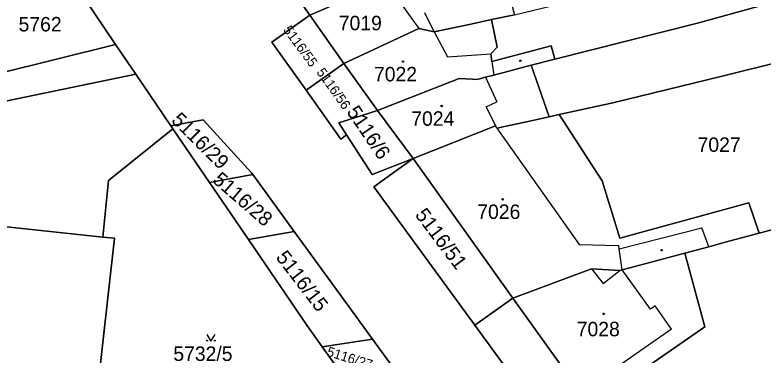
# Model space of a CAD drawing. Extents: x -596233 to -595156, y -1161235 to -1159375.
# Drawn here: x -595331.7 to -595243.9, y -1160472 to -1160432.1 of the extents above; entities that cross this region are included whole.
import ezdxf

# ---------------------------------------------------------------- set-up
doc = ezdxf.new("R2010")
doc.units = 0
for name, color, linetype in [('KN_CAR_KR', 7, 'Continuous'), ('KN_KULTURY', 7, 'Continuous'), ('KN_PARC_CIS_POZ', 7, 'Continuous'), ('KN_PARC_CIS_STAV', 7, 'Continuous'), ('KN_PARC_PLOCHA', 7, 'Continuous'), ('parcely_l', 7, 'Continuous')]:
    doc.layers.add(name, color=color, linetype=linetype)

msp = doc.modelspace()

# ---------------------------------------------------------------- linework, layer by layer
at = {"layer": 'KN_CAR_KR'}
for points in [[(-595288.01, -1160428.54), (-595284.3, -1160433.74)], [(-595282.52, -1160434.13), (-595283.59, -1160431.9)], [(-595282.52, -1160434.13), (-595280.96, -1160437.04)], [(-595280.96, -1160437.04), (-595275.87, -1160436.71)], [(-595275.74, -1160437.59), (-595275.5, -1160439.19)], [(-595276.48, -1160439.44), (-595275.14, -1160442.34)], [(-595276.4, -1160442.93), (-595275.14, -1160442.34)], [(-595276.4, -1160442.93), (-595275.31, -1160445.16)], [(-595275.13, -1160445.42), (-595265.47, -1160459.09)], [(-595260.77, -1160459.59), (-595251.06, -1160457.12)], [(-595250.26, -1160459.34), (-595251.06, -1160457.12)], [(-595265.47, -1160459.09), (-595260.84, -1160459.18)], [(-595260.77, -1160459.59), (-595260.84, -1160459.18)], [(-595260.43, -1160462.05), (-595260.77, -1160459.59)], [(-595264.02, -1160461.93), (-595262.68, -1160463.66)], [(-595262.68, -1160463.66), (-595260.7, -1160462.12)], [(-595257.11, -1160466.67), (-595260.43, -1160462.05)], [(-595256.55, -1160466.27), (-595257.11, -1160466.67)], [(-595254.62, -1160469.02), (-595256.55, -1160466.27)], [(-595254.62, -1160469.02), (-595264.73, -1160476.04)]]:
    msp.add_lwpolyline(points, dxfattribs=at)
at = {"layer": 'KN_KULTURY'}
msp.add_lwpolyline([(-595309.2118, -1160469.6516), (-595308.7118, -1160470.4016), (-595308.2118, -1160469.6516)], dxfattribs=at)
for centre, radius in [((-595286.18, -1160437.61), 0.09), ((-595286.18, -1160437.61), 0.0398), ((-595272.4, -1160437.52), 0.09), ((-595272.4, -1160437.52), 0.0398), ((-595281.64, -1160442.82), 0.09), ((-595281.64, -1160442.82), 0.0398), ((-595274.46, -1160453.77), 0.09), ((-595274.46, -1160453.77), 0.0398), ((-595255.8, -1160459.75), 0.09), ((-595255.8, -1160459.75), 0.0398), ((-595262.6, -1160467.21), 0.09), ((-595262.6, -1160467.21), 0.0398), ((-595309.162, -1160470.3514), 0.05), ((-595308.2626, -1160470.3514), 0.05)]:
    msp.add_circle(centre, radius, dxfattribs=at)
at = {"layer": 'KN_PARC_PLOCHA'}
for points in [[(-595334.41, -1160392.48), (-595328.83, -1160390.72), (-595328.44, -1160391.88), (-595323.41, -1160403.6), (-595321.29, -1160407.39), (-595317.06, -1160413.69), (-595315.81, -1160415.5), (-595318.48, -1160416.19), (-595309.95, -1160427.87), (-595307.38, -1160427.14), (-595305.39, -1160429.95), (-595300.92, -1160426.78), (-595297.09, -1160432.18), (-595301.56, -1160435.33), (-595297.55, -1160440.95), (-595293.45, -1160446.71), (-595292.81, -1160446.21), (-595289.79, -1160450.86), (-595284.99, -1160448.98), (-595289.59, -1160452.33), (-595277.72, -1160468.56), (-595260.2, -1160492.58)], [(-595287.14, -1160473.77), (-595289.76, -1160470.17), (-595291.7, -1160467.5), (-595298.95, -1160457.54), (-595303.81, -1160450.85), (-595303.95, -1160450.66), (-595309.64, -1160444.43), (-595313.41, -1160445.17), (-595317.54, -1160439.11), (-595319.94, -1160435.6), (-595326.06, -1160426.44), (-595332.18, -1160420.84)], [(-595395.86, -1160474.84), (-595397.98, -1160468.59), (-595400.07, -1160462.43), (-595402, -1160456.57), (-595317.54, -1160439.11), (-595313.41, -1160445.17), (-595313.18, -1160445.5), (-595320.75, -1160451.57), (-595321.43, -1160458.2), (-595334.2, -1160456.84), (-595334.81, -1160462.54), (-595353.42, -1160460.53), (-595354.19, -1160468.6), (-595335.67, -1160470.48), (-595336.6, -1160480.65)], [(-595336.6, -1160480.65), (-595335.67, -1160470.48), (-595354.19, -1160468.6), (-595353.42, -1160460.53), (-595334.81, -1160462.54), (-595334.2, -1160456.84), (-595321.43, -1160458.2), (-595320.06, -1160458.35), (-595322.1, -1160476.86)]]:
    msp.add_lwpolyline(points, dxfattribs=at)
for points in [[(-595178.3, -1160411.53), (-595213.55, -1160422.6), (-595251.59, -1160433.09), (-595268.34, -1160437.32), (-595268.75, -1160435.76), (-595275.74, -1160437.59), (-595275.87, -1160436.71), (-595275.1, -1160435.92), (-595275.77, -1160432.69), (-595273.07, -1160432.11), (-595253.1, -1160427.28), (-595222.89, -1160419.45), (-595201.46, -1160413.22), (-595179.94, -1160406.5)], [(-595176.22, -1160417.9), (-595190.25, -1160422.21), (-595204.49, -1160426.41), (-595216.34, -1160430.02), (-595233.44, -1160435.3), (-595234.03, -1160435.46), (-595241.3, -1160437.47), (-595248.85, -1160439.38), (-595261.52, -1160442.44), (-595267.81, -1160443.82), (-595268.99, -1160444.08), (-595271.1, -1160438.02), (-595268.34, -1160437.32), (-595251.59, -1160433.09), (-595213.55, -1160422.6), (-595178.3, -1160411.53)], [(-595274.7, -1160425.86), (-595282.87, -1160427.41), (-595288.01, -1160428.54), (-595288.17, -1160428.31), (-595297.09, -1160432.18), (-595300.92, -1160426.78), (-595292.78, -1160422.79), (-595286.38, -1160421.94), (-595285.46, -1160421.73), (-595283.3, -1160421.26), (-595276.37, -1160419.74), (-595275.46, -1160423.49)], [(-595319.94, -1160435.6), (-595340.92, -1160440.83), (-595341.72, -1160437.39), (-595343.33, -1160430.45), (-595326.06, -1160426.44)], [(-595273.07, -1160432.11), (-595275.77, -1160432.69), (-595278.2, -1160433.21), (-595282.52, -1160434.13), (-595284.3, -1160433.74), (-595293.12, -1160437.83), (-595297.09, -1160432.18), (-595288.17, -1160428.31), (-595288.01, -1160428.54), (-595282.87, -1160427.41), (-595274.7, -1160425.86), (-595273.72, -1160429.61)], [(-595293.12, -1160437.83), (-595297.55, -1160440.95), (-595301.56, -1160435.33), (-595297.09, -1160432.18)], [(-595268.34, -1160437.32), (-595271.1, -1160438.02), (-595275.5, -1160439.19), (-595276.48, -1160439.44), (-595277.46, -1160439.7), (-595278, -1160439.67), (-595279.58, -1160439.58), (-595289.15, -1160443.37), (-595293.12, -1160437.83), (-595284.3, -1160433.74), (-595282.52, -1160434.13), (-595278.2, -1160433.21), (-595275.77, -1160432.69), (-595275.1, -1160435.92), (-595275.87, -1160436.71), (-595275.74, -1160437.59), (-595268.75, -1160435.76)], [(-595317.54, -1160439.11), (-595402, -1160456.57), (-595404.06, -1160450.53), (-595341.72, -1160437.39), (-595340.92, -1160440.83), (-595319.94, -1160435.6)], [(-595230.65, -1160448.09), (-595235.34, -1160455.36), (-595244.36, -1160457.76), (-595245.57, -1160454.18), (-595260.72, -1160458.32), (-595262.79, -1160451.62), (-595267.81, -1160443.82), (-595261.52, -1160442.44), (-595248.85, -1160439.38), (-595241.3, -1160437.47), (-595234.03, -1160435.46)], [(-595289.15, -1160443.37), (-595293.72, -1160444.79), (-595292.81, -1160446.21), (-595293.45, -1160446.71), (-595297.55, -1160440.95), (-595293.12, -1160437.83)], [(-595268.99, -1160444.08), (-595271.11, -1160444.55), (-595275.13, -1160445.42), (-595275.31, -1160445.16), (-595284.99, -1160448.98), (-595289.15, -1160443.37), (-595279.58, -1160439.58), (-595278, -1160439.67), (-595277.46, -1160439.7), (-595276.48, -1160439.44), (-595275.5, -1160439.19), (-595271.1, -1160438.02)], [(-595284.99, -1160448.98), (-595289.79, -1160450.86), (-595292.81, -1160446.21), (-595293.72, -1160444.79), (-595289.15, -1160443.37)], [(-595244.36, -1160457.76), (-595248.32, -1160458.82), (-595250.26, -1160459.34), (-595253.06, -1160460.08), (-595259.54, -1160461.81), (-595260.43, -1160462.05), (-595260.7, -1160462.12), (-595264.02, -1160461.93), (-595273.27, -1160465.37), (-595284.99, -1160448.98), (-595275.31, -1160445.16), (-595275.13, -1160445.42), (-595271.11, -1160444.55), (-595268.99, -1160444.08), (-595267.81, -1160443.82), (-595262.79, -1160451.62), (-595260.72, -1160458.32), (-595245.57, -1160454.18)], [(-595303.81, -1160450.85), (-595308.89, -1160451.79), (-595313.18, -1160445.5), (-595313.41, -1160445.17), (-595309.64, -1160444.43), (-595303.95, -1160450.66)], [(-595308.89, -1160451.79), (-595304.32, -1160458.48), (-595297.46, -1160468.53), (-595295.64, -1160471.08), (-595292.65, -1160475.27), (-595287.63, -1160482.29), (-595286.17, -1160484.34), (-595291.19, -1160483.77), (-595304.64, -1160482.23), (-595305.5, -1160490.09), (-595324.43, -1160488.01), (-595323.19, -1160476.74), (-595322.1, -1160476.86), (-595320.06, -1160458.35), (-595321.43, -1160458.2), (-595320.75, -1160451.57), (-595313.18, -1160445.5)], [(-595273.27, -1160465.37), (-595277.72, -1160468.56), (-595289.59, -1160452.33), (-595284.99, -1160448.98)], [(-595298.95, -1160457.54), (-595304.32, -1160458.48), (-595308.89, -1160451.79), (-595303.81, -1160450.85)], [(-595258.48, -1160486.05), (-595263.82, -1160478.56), (-595263.23, -1160478.14), (-595263.59, -1160477.64), (-595250.72, -1160468.73), (-595253.06, -1160460.08), (-595250.26, -1160459.34), (-595248.32, -1160458.82), (-595244.36, -1160457.76), (-595235.34, -1160455.36), (-595231.23, -1160457.04), (-595226.61, -1160473.1), (-595258.08, -1160485.76)], [(-595289.76, -1160470.17), (-595295.64, -1160471.08), (-595297.46, -1160468.53), (-595304.32, -1160458.48), (-595298.95, -1160457.54), (-595291.7, -1160467.5)], [(-595263.82, -1160478.56), (-595264.19, -1160478.05), (-595265.33, -1160476.45), (-595273.27, -1160465.37), (-595264.02, -1160461.93), (-595260.7, -1160462.12), (-595260.43, -1160462.05), (-595259.54, -1160461.81), (-595253.06, -1160460.08), (-595250.72, -1160468.73), (-595263.59, -1160477.64), (-595263.23, -1160478.14)], [(-595263.82, -1160478.56), (-595258.48, -1160486.05), (-595255.46, -1160490.29), (-595260.2, -1160492.58), (-595277.72, -1160468.56), (-595273.27, -1160465.37), (-595265.33, -1160476.45), (-595264.19, -1160478.05)], [(-595286.85, -1160474.11), (-595292.65, -1160475.27), (-595295.64, -1160471.08), (-595289.76, -1160470.17), (-595287.14, -1160473.77)]]:
    msp.add_lwpolyline(points, close=True, dxfattribs=at)
at = {"layer": 'parcely_l'}
for points in [[(-595268.34, -1160437.32), (-595251.59, -1160433.09), (-595213.55, -1160422.6), (-595178.3, -1160411.53)], [(-595319.94, -1160435.6), (-595326.06, -1160426.44)], [(-595297.09, -1160432.18), (-595288.17, -1160428.31), (-595288.01, -1160428.54), (-595282.87, -1160427.41), (-595274.7, -1160425.86)], [(-595300.92, -1160426.78), (-595297.09, -1160432.18)], [(-595297.09, -1160432.18), (-595301.56, -1160435.33), (-595297.55, -1160440.95)], [(-595297.09, -1160432.18), (-595293.12, -1160437.83)], [(-595273.07, -1160432.11), (-595275.77, -1160432.69)], [(-595293.12, -1160437.83), (-595284.3, -1160433.74), (-595282.52, -1160434.13), (-595278.2, -1160433.21), (-595275.77, -1160432.69)], [(-595275.77, -1160432.69), (-595275.1, -1160435.92), (-595275.87, -1160436.71), (-595275.74, -1160437.59), (-595268.75, -1160435.76), (-595268.34, -1160437.32)], [(-595319.94, -1160435.6), (-595340.92, -1160440.83), (-595341.72, -1160437.39)], [(-595317.54, -1160439.11), (-595319.94, -1160435.6)], [(-595234.03, -1160435.46), (-595241.3, -1160437.47), (-595248.85, -1160439.38), (-595261.52, -1160442.44), (-595267.81, -1160443.82)], [(-595297.55, -1160440.95), (-595293.12, -1160437.83)], [(-595293.12, -1160437.83), (-595289.15, -1160443.37)], [(-595268.34, -1160437.32), (-595271.1, -1160438.02)], [(-595289.15, -1160443.37), (-595279.58, -1160439.58), (-595278, -1160439.67), (-595277.46, -1160439.7), (-595276.48, -1160439.44), (-595275.5, -1160439.19), (-595271.1, -1160438.02)], [(-595271.1, -1160438.02), (-595268.99, -1160444.08)], [(-595402, -1160456.57), (-595317.54, -1160439.11)], [(-595313.41, -1160445.17), (-595317.54, -1160439.11)], [(-595297.55, -1160440.95), (-595293.45, -1160446.71), (-595292.81, -1160446.21)], [(-595289.15, -1160443.37), (-595293.72, -1160444.79), (-595292.81, -1160446.21)], [(-595284.99, -1160448.98), (-595289.15, -1160443.37)], [(-595268.99, -1160444.08), (-595267.81, -1160443.82)], [(-595267.81, -1160443.82), (-595262.79, -1160451.62), (-595260.72, -1160458.32), (-595245.57, -1160454.18), (-595244.36, -1160457.76)], [(-595303.81, -1160450.85), (-595303.95, -1160450.66), (-595309.64, -1160444.43), (-595313.41, -1160445.17)], [(-595268.99, -1160444.08), (-595271.11, -1160444.55), (-595275.13, -1160445.42), (-595275.31, -1160445.16), (-595284.99, -1160448.98)], [(-595321.43, -1160458.2), (-595320.75, -1160451.57), (-595313.18, -1160445.5)], [(-595313.41, -1160445.17), (-595313.18, -1160445.5)], [(-595313.18, -1160445.5), (-595308.89, -1160451.79)], [(-595292.81, -1160446.21), (-595289.79, -1160450.86), (-595284.99, -1160448.98)], [(-595277.72, -1160468.56), (-595289.59, -1160452.33), (-595284.99, -1160448.98)], [(-595273.27, -1160465.37), (-595284.99, -1160448.98)], [(-595308.89, -1160451.79), (-595303.81, -1160450.85)], [(-595298.95, -1160457.54), (-595303.81, -1160450.85)], [(-595308.89, -1160451.79), (-595304.32, -1160458.48)], [(-595244.36, -1160457.76), (-595235.34, -1160455.36)], [(-595321.43, -1160458.2), (-595334.2, -1160456.84), (-595334.81, -1160462.54), (-595353.42, -1160460.53), (-595354.19, -1160468.6), (-595335.67, -1160470.48), (-595336.6, -1160480.65)], [(-595304.32, -1160458.48), (-595298.95, -1160457.54)], [(-595289.76, -1160470.17), (-595291.7, -1160467.5), (-595298.95, -1160457.54)], [(-595244.36, -1160457.76), (-595248.32, -1160458.82), (-595250.26, -1160459.34), (-595253.06, -1160460.08)], [(-595291.19, -1160483.77), (-595304.64, -1160482.23), (-595305.5, -1160490.09), (-595324.43, -1160488.01), (-595323.19, -1160476.74), (-595322.1, -1160476.86), (-595320.06, -1160458.35), (-595321.43, -1160458.2)], [(-595304.32, -1160458.48), (-595297.46, -1160468.53), (-595295.64, -1160471.08)], [(-595253.06, -1160460.08), (-595259.54, -1160461.81), (-595260.43, -1160462.05), (-595260.7, -1160462.12), (-595264.02, -1160461.93), (-595273.27, -1160465.37)], [(-595263.82, -1160478.56), (-595263.23, -1160478.14), (-595263.59, -1160477.64), (-595250.72, -1160468.73), (-595253.06, -1160460.08)], [(-595277.72, -1160468.56), (-595273.27, -1160465.37)], [(-595273.27, -1160465.37), (-595265.33, -1160476.45), (-595264.19, -1160478.05), (-595263.82, -1160478.56)], [(-595260.2, -1160492.58), (-595277.72, -1160468.56)], [(-595295.64, -1160471.08), (-595289.76, -1160470.17)], [(-595286.85, -1160474.11), (-595287.14, -1160473.77), (-595289.76, -1160470.17)], [(-595295.64, -1160471.08), (-595292.65, -1160475.27)]]:
    msp.add_lwpolyline(points, dxfattribs=at)

# ---------------------------------------------------------------- texts
at = {"layer": 'KN_PARC_CIS_POZ'}
for s, p in [('5762', (-595331.3066, -1160434.08)), ('7027', (-595251.5766, -1160448.21)), ('5732/5', (-595313.1366, -1160472.74))]:
    msp.add_text(s, height=1.7, dxfattribs=at).set_placement(p)
for s, height, rotation, p in [('5116/55', 1.14, 306.387394, (-595300.2943, -1160433.9209)), ('5116/56', 1.14, 305.60612, (-595296.3724, -1160438.8705)), ('5116/6', 1.7, 304.144356, (-595292.8435, -1160443.5136)), ('5116/29', 1.7, 315.205634, (-595313.4713, -1160444.6075)), ('5116/28', 1.7, 319.083482, (-595308.6321, -1160451.6886)), ('5116/51', 1.7, 307.043229, (-595284.8237, -1160455.617)), ('5116/15', 1.7, 307.502366, (-595301.1698, -1160460.6045)), ('5116/27', 1.14, 342.448774, (-595295.2031, -1160472.1141))]:
    msp.add_text(s, height=height, rotation=rotation, dxfattribs=at).set_placement(p)
at = {"layer": 'KN_PARC_CIS_STAV'}
for s, p in [('7019', (-595293.7066, -1160433.94)), ('7022', (-595289.5766, -1160439.94)), ('7024', (-595285.1966, -1160445.15)), ('7026', (-595277.4466, -1160456.08)), ('7028', (-595265.7666, -1160469.85))]:
    msp.add_text(s, height=1.7, dxfattribs=at).set_placement(p)

doc.saveas('drawing.dxf')
